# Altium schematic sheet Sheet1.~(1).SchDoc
size A4; SheetNumber: 1; SheetTotal: 1
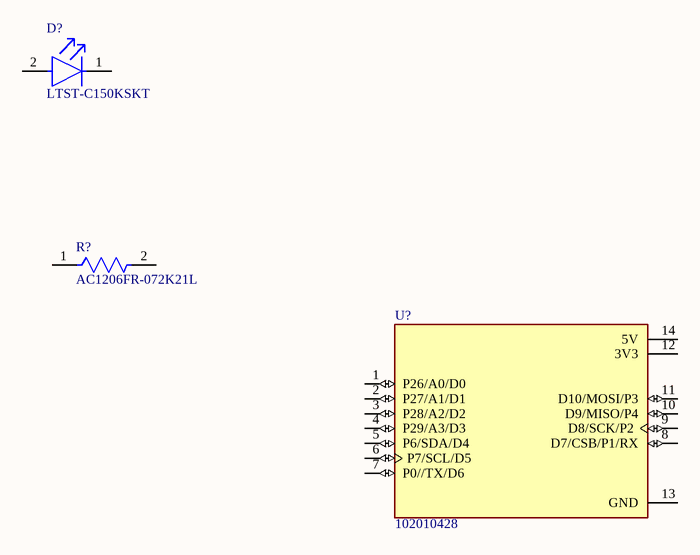
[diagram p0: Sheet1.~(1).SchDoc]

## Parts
D?  LTST-C150KSKT  [FP-LTST-C150KSKT-MFG]
R?  AC1206FR-072K21L  [FP-AC1206-MFG]
U?  102010428  [MODULE_102010428]

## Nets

Not connected (* = marked no-connect by the designer): D? 1(C) 2(A); R? 1 2; U? 1(P26/A0/D0) 2(P27/A1/D1) 3(P28/A2/D2) 4(P29/A3/D3) 5(P6/SDA/D4) 6(P7/SCL/D5) 7(P0//TX/D6) 8(D7/CSB/P1/RX) 9(D8/SCK/P2) 10(D9/MISO/P4) 11(D10/MOSI/P3) 12(3V3) 13(GND) 14(5V)

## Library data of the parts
D? = CMP-2000-06618-2: LED YELLOW CLEAR 1206 SMD; Power Rating: 75mW; Wavelength: 588nm; Forward Current: 30mA; Test Current: 20mA; Viewing Angle: 130°; Forward Voltage: 2.4V; Luminous Intensity: 60mcd; Lens Style: Diffused; Number of Elements: 1; Reverse Voltage: 5V; Lens Color: Colorless; Dominant Wavelength: 587nm
R? = CMP-03412-032679-1: RES SMD 2.21K OHM 1% 1/4W 1206; Manufacturer: Yageo; Automotive Grade: Grade 0; Description: AC1206 2.21KΩ 0.25W 1.00%; Voltage Rating: 200V; Tolerance: 0.01; Value: 2.21KΩ; Power Rating: 0.25W
U? = 102010428: RP2040 XIAO RP2040 series ARMÂ® CortexÂ®-M0+ MCU 32-Bit Embedded Evaluation Board; MF: Seeed Technology Co., Ltd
